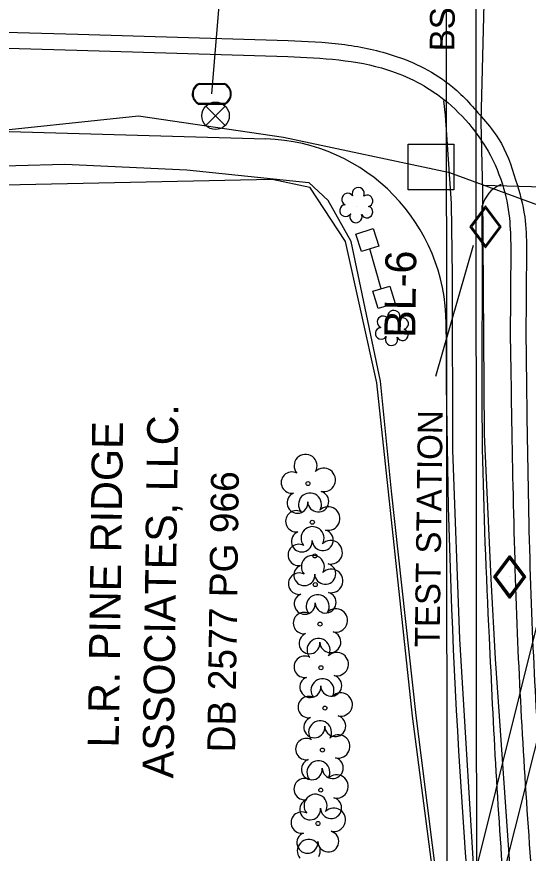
# Model space of a CAD drawing. Extents: x 1614427 to 1617186, y 896524 to 905462.
# Drawn here: x 1615917.9 to 1616000.6, y 904626.8 to 904762.1 of the extents above; entities that cross this region are included whole.
import ezdxf

# ---------------------------------------------------------------- set-up
doc = ezdxf.new("R2010")
doc.units = 0
for name, color, linetype in [('CTL Secondary Horizontal and Vertical CELL', 7, 'Continuous'), ('CTL Secondary Horizontal and Vertical Text', 7, 'Continuous'), ('Exist Building', 7, 'Continuous'), ('Exist Other Culture Sign', 7, 'Continuous'), ('Exist Property Deed Book Text', 7, 'Continuous'), ('Exist Property Owner Text', 7, 'Continuous'), ('Exist Right of Way Line', 7, 'Continuous'), ('Exist Roads Curbs', 7, 'Continuous'), ('Exist Roads EOP', 7, 'Continuous'), ('Exist Roads EOP Other', 7, 'Continuous'), ('Exist Roads EOP Text', 7, 'Continuous'), ('Exist Utilities Gas Meter CELL', 7, 'Continuous'), ('Exist Utilities Gas Meter Leader', 7, 'Continuous'), ('Exist Utilities Gas UG Line SUE LOS B', 7, 'Continuous'), ('Exist Utilities Gas Valve CELL', 7, 'Continuous'), ('Exist Utilities Power UG Cable SUE LOS B', 7, 'Continuous'), ('Exist Utilities Power UG Cable SUE LOS D', 7, 'Continuous'), ('Exist Utilities Telephone UG FO SUE LOS B', 7, 'Continuous'), ('Exist Utilities TV UG Cable SUE LOS B', 7, 'Continuous'), ('Exist Utilities TV UG Cable SUE LOS D', 7, 'Continuous'), ('Exist Utilities Water Meter CELL', 7, 'Continuous'), ('Exist Utilities Water UG Line SUE LOS B', 7, 'Continuous'), ('Exist Utilities Water Valve CELL', 7, 'Continuous'), ('Exist Vegetation Shrub CELL', 7, 'Continuous'), ('Exist Vegetation Tree CELL', 7, 'Continuous')]:
    doc.layers.add(name, color=color, linetype=linetype)

# ---------------------------------------------------------------- blocks, each defined once
blk = doc.blocks.new('CTL SECONDARY HORIZONTAL AND VERTICAL')
at = {"layer": 'CTL Secondary Horizontal and Vertical CELL'}
blk.add_line((0, 0), (0, 0), dxfattribs=at)
blk.add_lwpolyline([(-0.1043, 0.0004), (0.0005, 0.1052), (0.1055, 0.0002), (0.0007, -0.1047)], close=True, dxfattribs=at)
blk = doc.blocks.new('EXIST UTILITIES GAS VALVE')
at = {"layer": 'Exist Utilities Gas Valve CELL'}
blk.add_line((0, 0), (0, 0), dxfattribs=at)
blk.add_lwpolyline([(0, 0.0683), (-0.0508, 0), (0, -0.0683), (0.0508, 0), (0, 0.0683)], dxfattribs=at)
blk.add_lwpolyline([(0.0458, 0), (0, 0.0615), (-0.0458, 0), (0, -0.0615)], close=True, dxfattribs=at)
blk = doc.blocks.new('EXIST UTILITIES WATER METER')
at = {"layer": 'Exist Utilities Water Meter CELL'}
blk.add_line((0, 0), (0, 0), dxfattribs=at)
for points in [[(-0.0408, 0.034), (0.0408, 0.034)], [(-0.0408, 0.0312), (0.0408, 0.0312)], [(0.0408, -0.0312), (-0.0413, -0.0312)], [(0.0408, -0.034), (-0.0413, -0.034)]]:
    blk.add_lwpolyline(points, dxfattribs=at)
for centre, radius, start, end in [((-0.0261, -0.0001), 0.0371, 113.178, 245.9794), ((-0.0259, -0.0001), 0.0347, 115.3009, 243.7824), ((0.0259, 0), 0.0371, 293.6483, 66.3084), ((0.0261, 0), 0.0345, 295.1272, 64.8728)]:
    blk.add_arc(centre, radius, start, end, dxfattribs=at)
blk = doc.blocks.new('EXIST UTILITIES WATER VALVE')
at = {"layer": 'Exist Utilities Water Valve CELL'}
blk.add_lwpolyline([(0.0315, 0.0315), (-0.0315, -0.0315), (0, 0), (0.0315, -0.0315), (-0.0315, 0.0315)], dxfattribs=at)
blk.add_circle((0, 0), 0.0445, dxfattribs=at)

msp = doc.modelspace()

# ---------------------------------------------------------------- linework, layer by layer
at = {"layer": 'Exist Building'}
for points in [[(1615973.63, 904724.12), (1615972.73, 904726.95), (1615975.53, 904727.84), (1615976.43, 904725.01)], [(1615976.3, 904714.89), (1615975.46, 904717.69), (1615978.21, 904718.52), (1615979.05, 904715.71)]]:
    msp.add_lwpolyline(points, close=True, dxfattribs=at)
at = {"layer": 'Exist Other Culture Sign'}
msp.add_line((1615976.83, 904718.11), (1615975, 904724.56), dxfattribs=at)
at = {"layer": 'Exist Right of Way Line'}
msp.add_line((1615727.71, 904749.04), (1615958.17, 904742.34), dxfattribs=at)
for centre, radius, start, end in [((1615957.3, 904712.35), 30, 0.0031, 88.3333), ((1617163.21, 904712.42), 1175.92, 180.00313, 185.13333)]:
    msp.add_arc(centre, radius, start, end, dxfattribs=at)
at = {"layer": 'Exist Roads Curbs'}
msp.add_line((1615997.76, 904724.77), (1615997.69, 904709.96), dxfattribs=at)
msp.add_lwpolyline([(1615731.72, 904762.41), (1615771.48, 904761.25), (1615813.06, 904760.05), (1615852.28, 904758.96), (1615857.18, 904758.74), (1615860.14, 904758.73), (1615864.25, 904758.45), (1615886.59, 904757.88), (1615927.58, 904756.69), (1615961.72, 904755.66)], dxfattribs=at)
for points in [[(1615961.72, 904755.66), (1615969.97, 904755.12), (1615977.85, 904753.53), (1615986.94, 904748.73), (1615991.47, 904744.2), (1615993.66, 904741.09), (1615996.4, 904735.04), (1615997.53, 904729.52), (1615997.76, 904724.77)], [(1615997.69, 904709.96), (1615998.81, 904662.39), (1616001.48, 904618.72), (1616005.29, 904576.95), (1616010.16, 904533.14), (1616016.37, 904488.29), (1616024.44, 904443.46), (1616034.24, 904400.68), (1616040.86, 904375.22), (1616048.42, 904348.78), (1616057.52, 904320.31)]]:
    msp.add_spline(points, degree=3, dxfattribs=at)
at = {"layer": 'Exist Roads EOP'}
msp.add_line((1616000.33, 904724.66), (1616000.22, 904709.8), dxfattribs=at)
msp.add_lwpolyline([(1615731.93, 904764.88), (1615771.49, 904763.71), (1615813.15, 904762.65), (1615852.41, 904761.37), (1615886.78, 904760.44), (1615927.76, 904759.31), (1615961.77, 904758.26)], dxfattribs=at)
for points in [[(1615961.77, 904758.26), (1615970.44, 904757.67), (1615978.6, 904755.92), (1615988.36, 904750.75), (1615993.34, 904745.56), (1615995.8, 904742.36), (1615998.55, 904735.72), (1616000.02, 904729.73), (1616000.33, 904724.66)], [(1616000.22, 904709.8), (1616001.23, 904662.78), (1616003.98, 904618.91), (1616007.63, 904577.2), (1616012.51, 904533.44), (1616018.8, 904488.71), (1616027.01, 904443.97), (1616036.54, 904401.25), (1616043.36, 904375.84), (1616050.84, 904349.46), (1616059.98, 904321.05)]]:
    msp.add_spline(points, degree=3, dxfattribs=at)
at = {"layer": 'Exist Roads EOP Other'}
for p, q in [((1615987.22, 904746.18), (1615986.96, 904748.5)), ((1615988.18, 904731.91), (1615987.22, 904746.18)), ((1615996.06, 904734.92), (1615996.26, 904735.02)), ((1615988.33, 904720.19), (1615988.18, 904731.91)), ((1615993.21, 904718.78), (1615993.16, 904731.53)), ((1615988.35, 904718.98), (1615988.33, 904720.19))]:
    msp.add_line(p, q, dxfattribs=at)
msp.add_lwpolyline([(1615996.94, 904591.49), (1615994.32, 904598.08), (1615993.39, 904604.21), (1615992.17, 904617.87), (1615989.54, 904661.46), (1615988.4, 904692), (1615988.35, 904718.98)], dxfattribs=at)
msp.add_ellipse((1615998.1, 904730.25), major_axis=(-4.06, -3.1), ratio=0.998695, start_param=4.472094, end_param=5.376822, dxfattribs=at)
msp.add_spline([(1616000.59, 904594.89), (1615999.07, 904599.05), (1615998.19, 904604.66), (1615996.92, 904618.27), (1615994.31, 904661.69), (1615993.21, 904692.24), (1615993.21, 904718.78)], degree=3, dxfattribs=at)
at = {"layer": 'Exist Utilities Gas Meter Leader'}
msp.add_line((1615991.69, 904725.1), (1615985.57, 904703.92), dxfattribs=at)
at = {"layer": 'Exist Utilities Gas UG Line SUE LOS B'}
for points in [[(1616008.07, 904526.35), (1616004.5, 904556.45), (1616000.8, 904594.05), (1615997.92, 904620.35), (1615995.31, 904658.21), (1615994.57, 904671.15), (1615993.49, 904694.5), (1615993.22, 904733.75), (1615992.95, 904745.1), (1615994.07, 904787.68), (1615994.9, 904804.63), (1615996.12, 904832.64), (1615999.45, 904859.38), (1616007.42, 904913.09), (1616015.15, 904953.86), (1616027.47, 905003.13), (1616033.5, 905030.42), (1616046.64, 905085.14), (1616052.58, 905109.27)], [(1615993.18, 904734.88), (1616014.96, 904734.27), (1616052.35, 904733.61), (1616071.54, 904732.87), (1616107.32, 904732.28), (1616152.05, 904732.44), (1616189.32, 904733.19), (1616210.62, 904731.01), (1616260.06, 904733.9), (1616319.1, 904734.61)]]:
    msp.add_lwpolyline(points, dxfattribs=at)
at = {"layer": 'Exist Utilities Power UG Cable SUE LOS B'}
for points in [[(1615756.11, 904742.83), (1615765.06, 904741.57), (1615790.41, 904740.85), (1615828.69, 904739.93), (1615863.88, 904738.09), (1615901.82, 904737.62), (1615925.67, 904738.25), (1615945.39, 904737.36), (1615965.13, 904735.32)], [(1615989.54, 904605.88), (1615986.91, 904613.94), (1615982.45, 904649.04), (1615978.47, 904685.36), (1615976.69, 904703.14), (1615971.96, 904725.77), (1615968.26, 904732.4), (1615965.13, 904735.32)]]:
    msp.add_lwpolyline(points, dxfattribs=at)
at = {"layer": 'Exist Utilities Power UG Cable SUE LOS D'}
msp.add_line((1615987.51, 904605.51), (1615987.22, 904943.11), dxfattribs=at)
msp.add_lwpolyline([(1616024.11, 904362.27), (1616022.79, 904378.71), (1615987.51, 904605.51), (1616046.09, 904840.84)], dxfattribs=at)
at = {"layer": 'Exist Utilities Telephone UG FO SUE LOS B'}
msp.add_lwpolyline([(1616105.61, 904520.44), (1616089.41, 904571.33), (1616075.56, 904618.34), (1616065.14, 904654.86), (1616058.98, 904690.89), (1616058.73, 904702.96), (1616058.13, 904704.65), (1616053.77, 904709.72), (1616034.83, 904719.58), (1615987.91, 904736.85), (1615961, 904742.58), (1615937.6, 904746.04), (1615910.01, 904743.11), (1615897.44, 904742.07), (1615877.15, 904742.98), (1615846.81, 904745.02), (1615810.52, 904746.22), (1615776.87, 904748.95), (1615762.91, 904748.58), (1615760.94, 904747.82), (1615759.81, 904746.98), (1615759.35, 904745.38), (1615759.33, 904739.19)], dxfattribs=at)
at = {"layer": 'Exist Utilities TV UG Cable SUE LOS B'}
for points in [[(1615763.42, 904742.01), (1615756.08, 904737.65), (1615765.43, 904742.62), (1615791.02, 904741.56), (1615825.64, 904741.34), (1615846.23, 904740.88), (1615877.21, 904742.17), (1615897.32, 904741.38), (1615903.22, 904740.06), (1615906.69, 904736.71), (1615907.81, 904736.48), (1615910.73, 904734.8), (1615959.2, 904735.84), (1615965.27, 904734.52)], [(1615989.28, 904605.59), (1615988.23, 904607.22), (1615986.39, 904614.15), (1615981.85, 904648.94), (1615976.09, 904702.9), (1615971.02, 904725.73), (1615965.27, 904734.52)]]:
    msp.add_lwpolyline(points, dxfattribs=at)
at = {"layer": 'Exist Utilities TV UG Cable SUE LOS D'}
for points in [[(1615992.27, 904606.06), (1615992.03, 904943.11), (1615889.75, 905428.92)], [(1616028.66, 904363.47), (1615992.27, 904606.06), (1616050.93, 904839.81)]]:
    msp.add_lwpolyline(points, dxfattribs=at)
at = {"layer": 'Exist Utilities Water UG Line SUE LOS B'}
msp.add_line((1615949.42, 904749.62), (1615951.65, 904776.59), dxfattribs=at)
at = {"layer": 'Exist Vegetation Shrub CELL'}
for p, q in [((1615972.87, 904731.45), (1615972.87, 904731.45)), ((1615978.62, 904711.58), (1615978.62, 904711.58))]:
    msp.add_line(p, q, dxfattribs=at)
for centre, radius, start, end in [((1615973.1, 904733.49), 0.99, 334.8391, 200.4717), ((1615971.39, 904732.58), 0.968, 35.8908, 245.4216), ((1615974.54, 904732.32), 0.929, 284.4567, 126.0861), ((1615971.07, 904730.75), 0.955, 95.1099, 327.9534), ((1615974.51, 904730.52), 0.937, 204.9913, 73.4601), ((1615972.74, 904729.77), 0.984, 151.2797, 21.387), ((1615977.14, 904712.71), 0.968, 35.8908, 245.4216), ((1615978.85, 904713.62), 0.99, 334.8391, 200.4717), ((1615980.29, 904712.45), 0.929, 284.4567, 126.0861), ((1615976.82, 904710.88), 0.955, 95.1099, 327.9534), ((1615980.26, 904710.65), 0.937, 204.9913, 73.4601), ((1615978.49, 904709.9), 0.984, 151.2797, 21.387)]:
    msp.add_arc(centre, radius, start, end, dxfattribs=at)
at = {"layer": 'Exist Vegetation Tree CELL'}
for p, q in [((1615964.97, 904686.59), (1615964.97, 904686.59)), ((1615965.68, 904680.33), (1615965.68, 904680.33)), ((1615966.09, 904674.88), (1615966.09, 904674.88)), ((1615966.16, 904670.24), (1615966.16, 904670.24)), ((1615966.92, 904663.85), (1615966.92, 904663.85)), ((1615967.07, 904656.79), (1615967.07, 904656.79)), ((1615967.71, 904650.26), (1615967.71, 904650.26)), ((1615967.32, 904643.47), (1615967.32, 904643.47)), ((1615967.05, 904636.99), (1615967.05, 904636.99)), ((1615966.59, 904631.59), (1615966.59, 904631.59))]:
    msp.add_line(p, q, dxfattribs=at)
for centre in [(1615964.97, 904686.59), (1615965.68, 904680.33), (1615966.09, 904674.88), (1615966.16, 904670.24), (1615966.92, 904663.85), (1615967.07, 904656.79), (1615967.71, 904650.26), (1615967.32, 904643.47), (1615967.05, 904636.99), (1615966.59, 904631.59)]:
    msp.add_circle(centre, 0.326, dxfattribs=at)
for centre, radius, start, end in [((1615964.59, 904689.46), 1.86, 330.1651, 219.7134), ((1615967.52, 904687.18), 1.9, 257.1011, 134.1999), ((1615962.37, 904686.74), 1.73, 62.6636, 279.3457), ((1615963.27, 904683.47), 1.69, 111.5671, 6.231), ((1615965.3, 904683.2), 1.86, 330.1651, 219.7134), ((1615966.64, 904683.69), 1.7, 181.2822, 74.56), ((1615963.08, 904680.48), 1.73, 62.6636, 279.3457), ((1615968.23, 904680.92), 1.9, 257.1011, 134.1999), ((1615965.71, 904677.76), 1.86, 330.1651, 219.7134), ((1615963.98, 904677.21), 1.69, 111.5671, 6.231), ((1615967.36, 904677.43), 1.7, 181.2822, 74.56), ((1615963.49, 904675.04), 1.73, 62.6636, 279.3457), ((1615968.64, 904675.47), 1.9, 257.1011, 134.1999), ((1615965.77, 904673.11), 1.86, 330.1651, 219.7134), ((1615964.39, 904671.76), 1.69, 111.5671, 6.231), ((1615967.77, 904671.98), 1.7, 181.2822, 74.56), ((1615968.71, 904670.83), 1.9, 257.1011, 134.1999), ((1615963.55, 904670.39), 1.73, 62.6636, 279.3457), ((1615964.45, 904667.12), 1.69, 111.5671, 6.231), ((1615967.83, 904667.34), 1.7, 181.2822, 74.56), ((1615966.54, 904666.73), 1.86, 330.1651, 219.7134), ((1615969.47, 904664.44), 1.9, 257.1011, 134.1999), ((1615964.32, 904664.01), 1.73, 62.6636, 279.3457), ((1615965.22, 904660.73), 1.69, 111.5671, 6.231), ((1615968.59, 904660.95), 1.7, 181.2822, 74.56), ((1615966.68, 904659.66), 1.86, 330.1651, 219.7134), ((1615969.62, 904657.37), 1.9, 257.1011, 134.1999), ((1615964.46, 904656.94), 1.73, 62.6636, 279.3457), ((1615965.36, 904653.66), 1.69, 111.5671, 6.231), ((1615968.74, 904653.89), 1.7, 181.2822, 74.56), ((1615967.32, 904653.14), 1.86, 330.1651, 219.7134), ((1615970.26, 904650.85), 1.9, 257.1011, 134.1999), ((1615965.1, 904650.42), 1.73, 62.6636, 279.3457), ((1615966, 904647.14), 1.69, 111.5671, 6.231), ((1615969.38, 904647.36), 1.7, 181.2822, 74.56), ((1615966.93, 904646.34), 1.86, 330.1651, 219.7134), ((1615969.87, 904644.06), 1.9, 257.1011, 134.1999), ((1615964.71, 904643.62), 1.73, 62.6636, 279.3457), ((1615965.61, 904640.35), 1.69, 111.5671, 6.231), ((1615966.66, 904639.87), 1.86, 330.1651, 219.7134), ((1615968.99, 904640.57), 1.7, 181.2822, 74.56), ((1615964.44, 904637.15), 1.73, 62.6636, 279.3457), ((1615969.6, 904637.58), 1.9, 257.1011, 134.1999), ((1615966.2, 904634.46), 1.86, 330.1651, 219.7134), ((1615965.34, 904633.87), 1.69, 111.5671, 6.231), ((1615968.72, 904634.09), 1.7, 181.2822, 74.56), ((1615963.98, 904631.74), 1.73, 62.6636, 279.3457), ((1615969.14, 904632.18), 1.9, 257.1011, 134.1999), ((1615964.88, 904628.47), 1.69, 111.5671, 6.231), ((1615968.26, 904628.69), 1.7, 181.2822, 74.56), ((1615965.1, 904627.15), 1.86, 330.1651, 219.7134)]:
    msp.add_arc(centre, radius, start, end, dxfattribs=at)

# ---------------------------------------------------------------- block references
at = {"layer": 'CTL Secondary Horizontal and Vertical CELL', "xscale": 50, "yscale": 49.99999999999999, "rotation": 44.99999999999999}
msp.add_blockref('CTL SECONDARY HORIZONTAL AND VERTICAL', (1615984.85, 904737.76), dxfattribs=at)
msp.add_blockref('CTL SECONDARY HORIZONTAL AND VERTICAL', (1615984.85, 904737.76), dxfattribs=at)
at = {"layer": 'Exist Utilities Gas Valve CELL', "xscale": 50, "yscale": 50}
for p in [(1615993.69, 904728.12), (1615997.52, 904671.47), (1615997.64, 904671.48)]:
    msp.add_blockref('EXIST UTILITIES GAS VALVE', p, dxfattribs=at)
at = {"layer": 'Exist Utilities Water Meter CELL', "xscale": 50, "yscale": 50}
msp.add_blockref('EXIST UTILITIES WATER METER', (1615949.42, 904749.62), dxfattribs=at)
at = {"layer": 'Exist Utilities Water Valve CELL', "xscale": 50, "yscale": 50}
msp.add_blockref('EXIST UTILITIES WATER VALVE', (1615950.03, 904746.09), dxfattribs=at)

# ---------------------------------------------------------------- texts
at = {"layer": 'CTL Secondary Horizontal and Vertical Text'}
msp.add_text('BL-6', height=5, rotation=89.2167, dxfattribs=at).set_placement((1615982.31, 904710.13))
at = {"layer": 'Exist Property Deed Book Text'}
msp.add_text('DB 2577 PG 966', height=4.5, rotation=89.2167, dxfattribs=at).set_placement((1615953.19, 904643.07))
at = {"layer": 'Exist Property Owner Text'}
for s, p in [(' ASSOCIATES, LLC.', (1615943.18, 904637.01)), ('L.R. PINE RIDGE', (1615934.37, 904643.86))]:
    msp.add_text(s, height=5, rotation=89.2167, dxfattribs=at).set_placement(p)
at = {"layer": 'Exist Roads EOP Text'}
msp.add_text('BST', height=4, rotation=89.2167, dxfattribs=at).set_placement((1615988.63, 904756.49))
at = {"layer": 'Exist Utilities Gas Meter CELL'}
msp.add_text('TEST STATION', height=4, rotation=89.2167, dxfattribs=at).set_placement((1615986.24, 904660.08))

doc.saveas('drawing.dxf')
